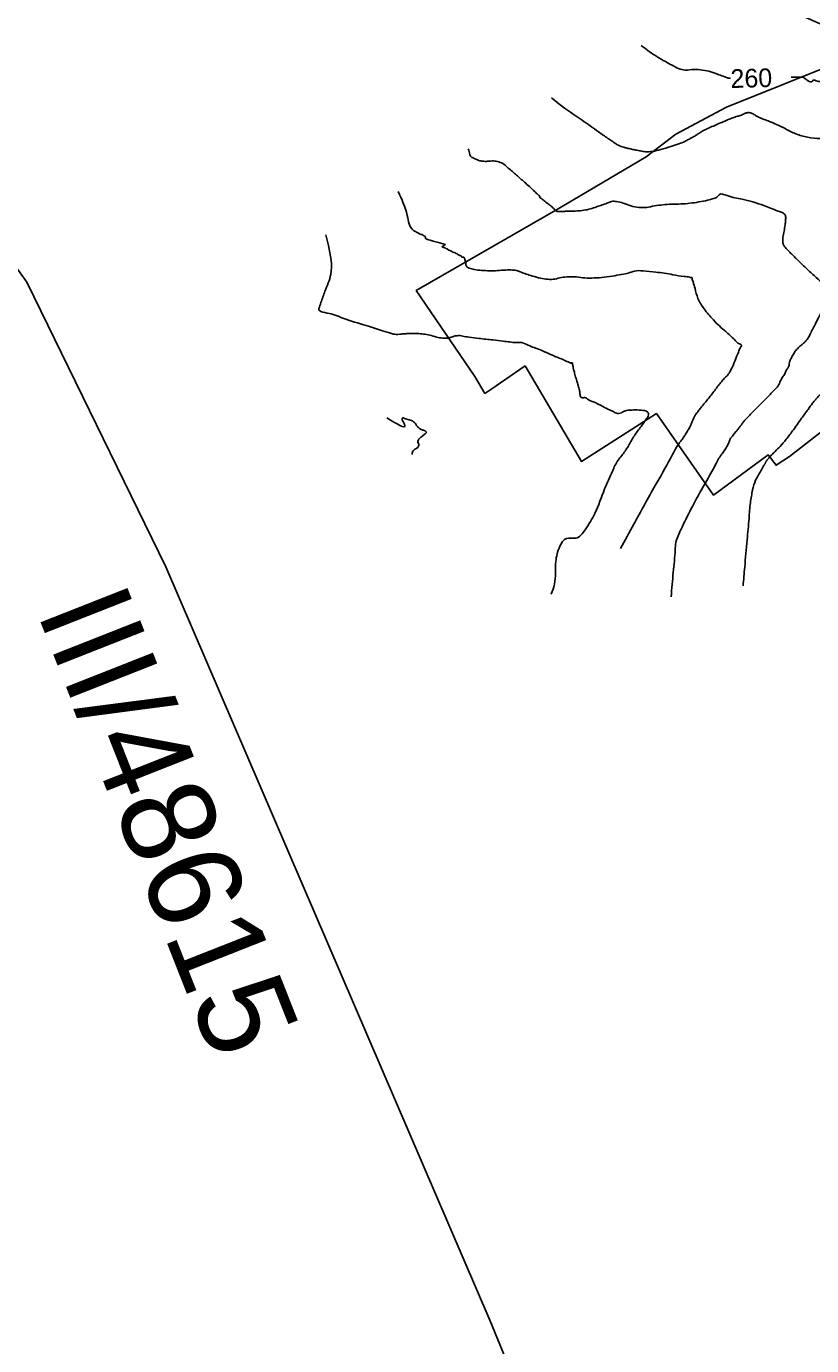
# Model space of a CAD drawing. Extents: x -478464 to -472469, y -1118040 to -1113785.
# Drawn here: x -476524.9 to -476356.8, y -1115724 to -1115441.7 of the extents above; entities that cross this region are included whole.
import ezdxf

# ---------------------------------------------------------------- set-up
doc = ezdxf.new("R2010")
doc.units = 0
for name, color, linetype in [('ObPÚ', 7, 'Continuous'), ('silnice', 7, 'Continuous'), ('Vrstevnice_hlavni', 7, 'Continuous'), ('Vrstevnice_popis', 7, 'Continuous'), ('Vrstevnice_vedlejsi', 7, 'Continuous')]:
    doc.layers.add(name, color=color, linetype=linetype)

msp = doc.modelspace()

# ---------------------------------------------------------------- linework, layer by layer
at = {"layer": 'ObPÚ'}
msp.add_lwpolyline([(-476350.14, -1115449), (-476375.02, -1115459.02), (-476385.85, -1115464.8), (-476392.23, -1115469.66), (-476411.03, -1115480.79), (-476441.42, -1115498.26), (-476428.9, -1115516.62), (-476426.71, -1115520.24), (-476425.46, -1115519.42), (-476418.11, -1115514.37), (-476406.06, -1115534.8), (-476390, -1115524.57), (-476377.76, -1115542), (-476366.06, -1115533.41), (-476364.38, -1115535.62), (-476361.53, -1115533.75), (-476342.91, -1115519.23)], dxfattribs=at)
at = {"layer": 'silnice'}
msp.add_lwpolyline([(-476261.922, -1115907.288), (-476366.595, -1115823.727), (-476390.845, -1115803.24), (-476425.665, -1115718.481), (-476494.983, -1115557.356), (-476524.795, -1115496.42), (-476580.823, -1115418.032), (-476641.911, -1115352.297), (-476741.891, -1115268.259), (-476824.194, -1115202.313), (-477005.33, -1115056.573), (-477039.82, -1115023.276), (-477040.729, -1115022.048)], dxfattribs=at)
at = {"layer": 'Vrstevnice_hlavni'}
for points in [[(-476374.118, -1115452.894), (-476374.632, -1115452.768), (-476375.379, -1115452.515), (-476376.616, -1115452.074), (-476378.342, -1115451.442), (-476380.123, -1115451.064), (-476381.96, -1115450.937), (-476383.851, -1115451.062), (-476386.654, -1115450.049), (-476390.368, -1115447.898), (-476393.306, -1115445.807)], [(-476361.162, -1115452.581), (-476360.502, -1115452.594), (-476360.124, -1115452.6), (-476359.698, -1115452.605), (-476359.225, -1115452.61), (-476358.899, -1115452.609), (-476358.72, -1115452.601), (-476358.688, -1115452.587), (-476358.473, -1115452.713), (-476358.077, -1115452.978), (-476357.499, -1115453.383), (-476357.043, -1115453.576), (-476356.711, -1115453.558), (-476356.502, -1115453.327), (-476356.285, -1115453.216), (-476356.059, -1115453.223), (-476355.825, -1115453.35), (-476354.616, -1115453.553), (-476352.432, -1115453.833), (-476349.273, -1115454.189), (-476346.274, -1115454.744), (-476343.436, -1115455.496), (-476340.758, -1115456.445), (-476338.338, -1115457.257), (-476336.174, -1115457.932), (-476334.267, -1115458.468), (-476331.855, -1115459.164), (-476328.939, -1115460.019), (-476325.519, -1115461.034), (-476322.732, -1115461.848), (-476320.579, -1115462.463), (-476319.06, -1115462.877), (-476317.799, -1115463.096), (-476316.797, -1115463.12), (-476316.054, -1115462.948), (-476315.267, -1115462.732), (-476314.436, -1115462.471), (-476313.562, -1115462.166), (-476312.761, -1115461.86), (-476312.034, -1115461.555), (-476311.38, -1115461.249), (-476310.693, -1115460.985), (-476309.972, -1115460.764), (-476309.217, -1115460.585), (-476308.367, -1115460.371), (-476307.42, -1115460.122), (-476306.377, -1115459.838), (-476305.206, -1115459.571), (-476303.906, -1115459.322), (-476302.479, -1115459.089), (-476301.067, -1115458.819), (-476299.672, -1115458.512), (-476298.293, -1115458.167), (-476297.154, -1115457.84), (-476296.253, -1115457.53), (-476295.591, -1115457.237), (-476294.783, -1115456.948), (-476293.83, -1115456.665), (-476292.73, -1115456.386), (-476291.92, -1115456.156), (-476291.4, -1115455.977), (-476291.168, -1115455.846), (-476290.893, -1115455.713), (-476290.575, -1115455.576), (-476290.213, -1115455.436), (-476290.094, -1115455.451), (-476290.219, -1115455.622), (-476290.588, -1115455.948), (-476290.881, -1115456.193), (-476291.098, -1115456.355), (-476291.24, -1115456.434), (-476291.722, -1115456.646), (-476292.544, -1115456.989), (-476293.708, -1115457.465), (-476294.611, -1115457.835), (-476295.255, -1115458.098), (-476295.638, -1115458.254), (-476296.311, -1115458.524), (-476297.274, -1115458.906), (-476298.527, -1115459.402), (-476300.239, -1115460.023), (-476302.409, -1115460.771), (-476305.038, -1115461.644), (-476306.986, -1115462.279), (-476308.253, -1115462.673), (-476308.839, -1115462.829), (-476309.599, -1115463.049), (-476310.531, -1115463.335), (-476311.637, -1115463.685), (-476312.81, -1115465.138), (-476314.05, -1115467.692), (-476315.357, -1115471.347), (-476316.514, -1115474.339), (-476317.52, -1115476.668), (-476318.375, -1115478.334), (-476319.029, -1115479.573), (-476319.48, -1115480.384)], [(-476442.249, -1115533.315), (-476442.258, -1115533.223), (-476442.035, -1115532.45), (-476441.322, -1115531.991), (-476440.926, -1115531.554), (-476440.848, -1115531.138), (-476441.086, -1115530.744), (-476441.04, -1115530.317), (-476440.708, -1115529.858), (-476440.091, -1115529.366), (-476439.638, -1115528.987), (-476439.349, -1115528.72), (-476439.224, -1115528.565), (-476439.347, -1115528.386), (-476439.718, -1115528.183), (-476440.335, -1115527.956), (-476440.852, -1115527.632), (-476441.268, -1115527.211), (-476441.584, -1115526.693), (-476441.969, -1115526.298), (-476442.426, -1115526.027), (-476442.953, -1115525.878), (-476443.443, -1115525.735), (-476443.895, -1115525.597), (-476444.309, -1115525.465), (-476444.44, -1115525.662), (-476444.286, -1115526.188), (-476443.849, -1115527.043), (-476447.74, -1115525.503)]]:
    msp.add_spline(points, degree=3, dxfattribs=at)
at = {"layer": 'Vrstevnice_vedlejsi'}
for points in [[(-476363.771, -1115433.002), (-476361.824, -1115435.483), (-476360.478, -1115437.317), (-476359.554, -1115438.574), (-476359.053, -1115439.254), (-476358.975, -1115439.358), (-476357.995, -1115439.829), (-476356.115, -1115440.666), (-476353.333, -1115441.869), (-476351.103, -1115442.874), (-476349.425, -1115443.68), (-476348.298, -1115444.288), (-476347.182, -1115444.735), (-476346.075, -1115445.02), (-476344.979, -1115445.144), (-476343.938, -1115445.336), (-476342.954, -1115445.597), (-476342.024, -1115445.927), (-476339.802, -1115446.597), (-476336.287, -1115447.609), (-476331.48, -1115448.962), (-476327.658, -1115450.047), (-476324.822, -1115450.863), (-476322.972, -1115451.412), (-476321.329, -1115451.89), (-476319.894, -1115452.296), (-476318.667, -1115452.631), (-476317.589, -1115452.899), (-476316.66, -1115453.101), (-476315.881, -1115453.236), (-476315.249, -1115453.177), (-476314.764, -1115452.922), (-476314.427, -1115452.472), (-476313.932, -1115452.125), (-476313.279, -1115451.881), (-476312.47, -1115451.74), (-476311.268, -1115451.729), (-476309.676, -1115451.848)], [(-476412.487, -1115456.977), (-476410.913, -1115458.262), (-476405.882, -1115461.815), (-476402.37, -1115464.29), (-476400.376, -1115465.685), (-476399.9, -1115466), (-476399.472, -1115466.293), (-476399.093, -1115466.564), (-476398.763, -1115466.813), (-476398.4, -1115467.035), (-476398.006, -1115467.232), (-476397.581, -1115467.402), (-476397, -1115467.583), (-476396.264, -1115467.775), (-476395.373, -1115467.977), (-476394.42, -1115468.176), (-476393.405, -1115468.369), (-476392.328, -1115468.558), (-476390.887, -1115468.463), (-476389.082, -1115468.084), (-476386.914, -1115467.422), (-476385.197, -1115466.84), (-476383.932, -1115466.337), (-476383.118, -1115465.915), (-476382.467, -1115465.566), (-476381.978, -1115465.291), (-476381.65, -1115465.088), (-476381.304, -1115464.864), (-476380.937, -1115464.618), (-476380.551, -1115464.349), (-476379.903, -1115463.998), (-476378.994, -1115463.563), (-476377.824, -1115463.044), (-476376.623, -1115462.523), (-476375.392, -1115462)], [(-476375.392, -1115462), (-476374.129, -1115461.473), (-476373.218, -1115461.118), (-476372.659, -1115460.933), (-476372.45, -1115460.919), (-476372.087, -1115460.802), (-476371.568, -1115460.58), (-476370.895, -1115460.255), (-476370.204, -1115460.181), (-476369.496, -1115460.36), (-476368.77, -1115460.791), (-476367.914, -1115461.219), (-476366.926, -1115461.642), (-476365.807, -1115462.062), (-476364.304, -1115462.716), (-476362.417, -1115463.605), (-476360.145, -1115464.728), (-476357.641, -1115465.438), (-476354.904, -1115465.734), (-476351.935, -1115465.618), (-476349.849, -1115465.502), (-476348.647, -1115465.387), (-476348.329, -1115465.272), (-476347.968, -1115465.34), (-476347.565, -1115465.59), (-476347.119, -1115466.023), (-476346.516, -1115466.573), (-476345.755, -1115467.242), (-476344.837, -1115468.03), (-476344.033, -1115469.141), (-476343.343, -1115470.576), (-476342.768, -1115472.335), (-476342.342, -1115473.633), (-476342.065, -1115474.468), (-476341.938, -1115474.841), (-476341.36, -1115475.721), (-476340.333, -1115477.106), (-476338.856, -1115478.997), (-476337.825, -1115480.446), (-476337.242, -1115481.454), (-476337.106, -1115482.02), (-476336.708, -1115482.699), (-476336.047, -1115483.489), (-476335.123, -1115484.392), (-476334.613, -1115485.234), (-476334.515, -1115486.014), (-476334.83, -1115486.732), (-476335.165, -1115487.505), (-476335.519, -1115488.332), (-476335.893, -1115489.212), (-476336.181, -1115489.954), (-476336.384, -1115490.556), (-476336.5, -1115491.018), (-476336.678, -1115491.638), (-476336.918, -1115492.417), (-476337.22, -1115493.354), (-476337.658, -1115494.21), (-476338.234, -1115494.984), (-476338.946, -1115495.678), (-476339.549, -1115496.226), (-476340.042, -1115496.627), (-476340.425, -1115496.883), (-476340.759, -1115497.34), (-476341.045, -1115497.997), (-476341.282, -1115498.856), (-476341.828, -1115499.854), (-476342.682, -1115500.993), (-476343.846, -1115502.272), (-476344.811, -1115503.411), (-476345.578, -1115504.411), (-476346.146, -1115505.272), (-476346.807, -1115506.216), (-476347.56, -1115507.242), (-476348.405, -1115508.352), (-476349.595, -1115510.321), (-476351.128, -1115513.152), (-476353.005, -1115516.842), (-476354.314, -1115519.344), (-476355.055, -1115520.656), (-476355.227, -1115520.78), (-476355.538, -1115521.104), (-476355.989, -1115521.629), (-476356.58, -1115522.354), (-476357.559, -1115523.662), (-476358.927, -1115525.554), (-476360.684, -1115528.028), (-476362.218, -1115530.038), (-476363.528, -1115531.584), (-476364.614, -1115532.666), (-476365.375, -1115533.438), (-476365.811, -1115533.898), (-476365.922, -1115534.047), (-476366.035, -1115534.195), (-476366.151, -1115534.34), (-476366.269, -1115534.483), (-476366.37, -1115534.607), (-476366.453, -1115534.711)], [(-476390.415, -1115480.123), (-476392.093, -1115480.442), (-476393.773, -1115480.449), (-476395.455, -1115480.141), (-476397.138, -1115479.52), (-476398.521, -1115479.202), (-476399.606, -1115479.187), (-476400.391, -1115479.474), (-476401.353, -1115479.819), (-476402.494, -1115480.221), (-476403.813, -1115480.681), (-476405.189, -1115481.004), (-476406.622, -1115481.191), (-476408.113, -1115481.24), (-476409.287, -1115481.28), (-476410.144, -1115481.31), (-476410.685, -1115481.331), (-476411.093, -1115481.319), (-476411.368, -1115481.273), (-476411.51, -1115481.194), (-476411.664, -1115481.065), (-476411.83, -1115480.886), (-476412.009, -1115480.658), (-476412.452, -1115480.262), (-476413.159, -1115479.699), (-476414.132, -1115478.968), (-476414.756, -1115478.466), (-476415.033, -1115478.195), (-476414.961, -1115478.152), (-476415.298, -1115477.773), (-476416.042, -1115477.057), (-476417.195, -1115476.004), (-476418.233, -1115475.067), (-476419.157, -1115474.246), (-476419.967, -1115473.541), (-476420.822, -1115472.803), (-476421.721, -1115472.032), (-476422.665, -1115471.228), (-476423.717, -1115470.72), (-476424.877, -1115470.508), (-476426.145, -1115470.593), (-476427.196, -1115470.561), (-476428.028, -1115470.413), (-476428.643, -1115470.148), (-476429.106, -1115469.938), (-476429.418, -1115469.785), (-476429.579, -1115469.688), (-476430.087, -1115468.492), (-476430.298, -1115467.927)], [(-476435.156, -1115488.388), (-476435.158, -1115488.388), (-476435.557, -1115488.278), (-476436.352, -1115488.058), (-476437.543, -1115487.729), (-476438.431, -1115487.476), (-476439.016, -1115487.299), (-476439.298, -1115487.198), (-476439.46, -1115487.083), (-476439.502, -1115486.954), (-476439.423, -1115486.81), (-476439.571, -1115486.628), (-476439.947, -1115486.406), (-476440.549, -1115486.147), (-476441.093, -1115485.887), (-476441.577, -1115485.629), (-476442.002, -1115485.371), (-476443.347, -1115482.202), (-476445.27, -1115477.051)], [(-476386.868, -1115563.77), (-476386.404, -1115558.49), (-476385.983, -1115553.73), (-476385.843, -1115552.17), (-476384.718, -1115549.256), (-476382.607, -1115544.988), (-476379.51, -1115539.367), (-476377.347, -1115535.488), (-476376.117, -1115533.352), (-476375.821, -1115532.959), (-476375.527, -1115532.539), (-476375.236, -1115532.091), (-476374.948, -1115531.616), (-476374.711, -1115531.173), (-476374.526, -1115530.763), (-476374.393, -1115530.385), (-476374.22, -1115530.026), (-476374.008, -1115529.686), (-476373.756, -1115529.365), (-476373.437, -1115528.968), (-476373.052, -1115528.496), (-476372.6, -1115527.948), (-476372.158, -1115527.393), (-476371.726, -1115526.831), (-476371.304, -1115526.261), (-476370.255, -1115525.116), (-476368.58, -1115523.398), (-476366.278, -1115521.105), (-476364.681, -1115519.417), (-476363.788, -1115518.333), (-476363.599, -1115517.854), (-476363.38, -1115517.403), (-476363.131, -1115516.981), (-476362.852, -1115516.586), (-476362.624, -1115516.208), (-476362.447, -1115515.848), (-476362.32, -1115515.506), (-476362.183, -1115515.228), (-476362.036, -1115515.015), (-476361.879, -1115514.866), (-476361.743, -1115514.589), (-476361.628, -1115514.182), (-476361.535, -1115513.647), (-476361.302, -1115513.008), (-476360.931, -1115512.265), (-476360.421, -1115511.418), (-476359.844, -1115510.674), (-476359.201, -1115510.032), (-476358.493, -1115509.493), (-476357.886, -1115508.861), (-476357.381, -1115508.138), (-476356.978, -1115507.323), (-476356.457, -1115506.284), (-476355.818, -1115505.02), (-476355.061, -1115503.532), (-476354.274, -1115502.169), (-476353.457, -1115500.932), (-476352.611, -1115499.821), (-476352.458, -1115498.76), (-476353, -1115497.749), (-476354.236, -1115496.789), (-476355.796, -1115495.443), (-476357.679, -1115493.713), (-476359.885, -1115491.598), (-476361.477, -1115490.015), (-476362.455, -1115488.962), (-476362.82, -1115488.441), (-476362.968, -1115487.633), (-476362.899, -1115486.539), (-476362.614, -1115485.158), (-476362.433, -1115483.976), (-476362.356, -1115482.993), (-476362.383, -1115482.21), (-476363.943, -1115481.232), (-476367.039, -1115480.058), (-476371.668, -1115478.69), (-476374.855, -1115477.913), (-476376.599, -1115477.729), (-476376.9, -1115478.137), (-476377.722, -1115478.533), (-476379.064, -1115478.919), (-476380.926, -1115479.294), (-476382.829, -1115479.558), (-476384.771, -1115479.713), (-476386.754, -1115479.758), (-476388.635, -1115479.895), (-476390.415, -1115480.123)], [(-476408.095, -1115513.705), (-476408.196, -1115513.728), (-476408.268, -1115513.743), (-476408.31, -1115513.748), (-476408.321, -1115513.745), (-476409.488, -1115513.249), (-476411.808, -1115512.262), (-476415.283, -1115510.782), (-476417.744, -1115509.807), (-476419.192, -1115509.336), (-476419.626, -1115509.37), (-476420.137, -1115509.365), (-476420.725, -1115509.322), (-476421.39, -1115509.24), (-476422.819, -1115509.072), (-476425.012, -1115508.818), (-476427.967, -1115508.478), (-476430.119, -1115508.208), (-476431.467, -1115508.009), (-476432.012, -1115507.881), (-476432.677, -1115507.898), (-476433.462, -1115508.059), (-476434.367, -1115508.365), (-476435.455, -1115508.435), (-476436.726, -1115508.27), (-476438.179, -1115507.87), (-476439.551, -1115507.597), (-476440.841, -1115507.45), (-476442.049, -1115507.43), (-476443.148, -1115507.446), (-476444.139, -1115507.499), (-476445.02, -1115507.589), (-476445.738, -1115507.612), (-476446.294, -1115507.568), (-476446.687, -1115507.457), (-476448.623, -1115506.848), (-476452.103, -1115505.741), (-476457.127, -1115504.136), (-476460.496, -1115503.043), (-476462.21, -1115502.463), (-476462.27, -1115502.394), (-476462.297, -1115502.311), (-476462.291, -1115502.212), (-476462.252, -1115502.098), (-476461.808, -1115500.826), (-476460.959, -1115498.396), (-476459.705, -1115494.808), (-476460.221, -1115488.599), (-476460.746, -1115486.336)], [(-476381.496, -1115524.576), (-476381.058, -1115524.018), (-476380.504, -1115523.329), (-476379.834, -1115522.508), (-476379.049, -1115521.557), (-476378.281, -1115520.592), (-476377.53, -1115519.614), (-476376.797, -1115518.624), (-476376.099, -1115517.755), (-476375.438, -1115517.009), (-476374.812, -1115516.386), (-476374.17, -1115515.401), (-476373.512, -1115514.054), (-476372.838, -1115512.345), (-476372.335, -1115511.13), (-476372.003, -1115510.408), (-476371.84, -1115510.178), (-476371.827, -1115509.979), (-476371.962, -1115509.811), (-476372.246, -1115509.672), (-476373.318, -1115508.746), (-476375.177, -1115507.032), (-476377.825, -1115504.531), (-476379.802, -1115502.156), (-476381.109, -1115499.909), (-476381.745, -1115497.789), (-476382.17, -1115496.348), (-476382.383, -1115495.585), (-476382.386, -1115495.5), (-476382.424, -1115495.445), (-476382.499, -1115495.418), (-476382.61, -1115495.421), (-476382.691, -1115495.424), (-476382.74, -1115495.427), (-476382.759, -1115495.431), (-476382.784, -1115495.429), (-476382.813, -1115495.421), (-476382.848, -1115495.408), (-476384.079, -1115495.216), (-476386.506, -1115494.845), (-476390.13, -1115494.294), (-476392.866, -1115494.036), (-476394.717, -1115494.071), (-476395.681, -1115494.399), (-476397.081, -1115494.728), (-476398.917, -1115495.058), (-476401.19, -1115495.39), (-476403.316, -1115495.546), (-476405.295, -1115495.527), (-476407.128, -1115495.333), (-476408.815, -1115495.309), (-476410.355, -1115495.455), (-476411.749, -1115495.772), (-476413.243, -1115495.824), (-476414.837, -1115495.61), (-476416.531, -1115495.132), (-476417.908, -1115494.707), (-476418.968, -1115494.337), (-476419.711, -1115494.02), (-476420.805, -1115493.856), (-476422.249, -1115493.843), (-476424.045, -1115493.982), (-476425.766, -1115494.011), (-476427.414, -1115493.928), (-476428.987, -1115493.735), (-476430.078, -1115493.424), (-476430.686, -1115492.995), (-476430.812, -1115492.449), (-476430.915, -1115491.994), (-476430.996, -1115491.631), (-476431.055, -1115491.359), (-476431.167, -1115491.175), (-476431.332, -1115491.079), (-476431.551, -1115491.071), (-476431.695, -1115491.04), (-476431.765, -1115490.986), (-476431.759, -1115490.908), (-476432.056, -1115490.718), (-476432.657, -1115490.416), (-476433.561, -1115490.002), (-476434.225, -1115489.683), (-476434.65, -1115489.461), (-476434.835, -1115489.334), (-476434.976, -1115489.24), (-476435.074, -1115489.18), (-476435.128, -1115489.153), (-476435.254, -1115489.108), (-476435.453, -1115489.045), (-476435.725, -1115488.965), (-476435.863, -1115488.891), (-476435.867, -1115488.824), (-476435.736, -1115488.763), (-476435.599, -1115488.688), (-476435.455, -1115488.598), (-476435.304, -1115488.493), (-476435.204, -1115488.423), (-476435.156, -1115488.388)], [(-476412.508, -1115563.171), (-476411.848, -1115561.069), (-476411.539, -1115556.209), (-476410.675, -1115552.946), (-476409.255, -1115551.281), (-476407.279, -1115551.213), (-476405.259, -1115549.425), (-476403.194, -1115545.916), (-476401.086, -1115540.688), (-476399.421, -1115536.885), (-476398.2, -1115534.51), (-476397.423, -1115533.561), (-476396.715, -1115532.584), (-476396.077, -1115531.58), (-476395.509, -1115530.549), (-476394.886, -1115529.538), (-476394.208, -1115528.545), (-476393.474, -1115527.573), (-476392.807, -1115526.632), (-476392.208, -1115525.724), (-476391.677, -1115524.848), (-476391.892, -1115524.233), (-476392.853, -1115523.879), (-476394.56, -1115523.785), (-476395.9, -1115523.836), (-476396.873, -1115524.031), (-476397.48, -1115524.372), (-476398.046, -1115524.521), (-476398.573, -1115524.479), (-476399.059, -1115524.246), (-476400.034, -1115523.767), (-476401.498, -1115523.043), (-476403.451, -1115522.073), (-476404.773, -1115521.441), (-476405.463, -1115521.147), (-476405.521, -1115521.191), (-476405.642, -1115521.2), (-476405.825, -1115521.174), (-476406.072, -1115521.112), (-476406.25, -1115520.912), (-476406.358, -1115520.574), (-476406.399, -1115520.096), (-476406.555, -1115519.343), (-476406.827, -1115518.313), (-476407.215, -1115517.007), (-476407.516, -1115515.936), (-476407.728, -1115515.1), (-476407.853, -1115514.499), (-476407.938, -1115514.074), (-476407.983, -1115513.826), (-476407.988, -1115513.754), (-476408.025, -1115513.714), (-476408.095, -1115513.705)], [(-476397.702, -1115553.445), (-476394.813, -1115548.217), (-476390.245, -1115539.924), (-476387.028, -1115534.168), (-476385.162, -1115530.949), (-476384.647, -1115530.266), (-476384.137, -1115529.535), (-476383.631, -1115528.757), (-476383.13, -1115527.931), (-476382.719, -1115527.161), (-476382.397, -1115526.448), (-476382.166, -1115525.791), (-476381.866, -1115525.167), (-476381.496, -1115524.576)], [(-476366.453, -1115534.711), (-476366.519, -1115534.795), (-476366.575, -1115534.884), (-476366.62, -1115534.978), (-476366.655, -1115535.077), (-476366.704, -1115535.185), (-476366.766, -1115535.301), (-476366.841, -1115535.425), (-476366.917, -1115535.543), (-476366.994, -1115535.653), (-476367.072, -1115535.756), (-476367.394, -1115536.315), (-476367.961, -1115537.331), (-476368.772, -1115538.804), (-476369.413, -1115540.903), (-476369.885, -1115543.629), (-476370.186, -1115546.981), (-476370.595, -1115551.582), (-476371.111, -1115557.431), (-476371.459, -1115561.384)]]:
    msp.add_spline(points, degree=3, dxfattribs=at)

# ---------------------------------------------------------------- texts
at = {"layer": 'silnice'}
msp.add_text('III/48615', height=20, rotation=291.50868, dxfattribs=at).set_placement((-476522.739, -1115566.913))
at = {"layer": 'Vrstevnice_popis'}
msp.add_text(' 260 ', height=4, rotation=1.48492, dxfattribs=at).set_placement((-476375.588, -1115454.953))

doc.saveas('drawing.dxf')
